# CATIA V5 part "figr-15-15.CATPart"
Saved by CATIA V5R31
Part number: Part1
Bounding box of the stored display mesh (mm): x -75 to 75, y -66.397 to 33.603, z 0 to 1
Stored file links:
  D:\PROJECTS\Project 2021\US EDITION\CATIA V5 6R 2021\Resources\Part Files\c15_catia_v5_6r2021_prt\figr-15-15.CATPart
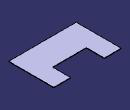
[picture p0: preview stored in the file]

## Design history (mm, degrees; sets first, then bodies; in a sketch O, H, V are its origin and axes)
SheetMetalParameters1: Thickness 1, BendRadius 1, KFactor 0.325257 {= log(min(100,max(20*SheetMetalParameters1.BendRadius,SheetMetalParameters1.Thickness)/SheetMetalParameters1.Thickness))/log(100)/2}, ReliefRadialLength 1, ReliefAxialLength 2, MinimumBendRadius 0
Body1 (main body)
  Sketch1 on xy-plane, origin (0, 0, 0), H (1, 0, 0), V (0, 1, 0)
    line L1 (-37.5, 33.6029) -> (-37.5, -6.3971)
    line L2 (-37.5, -6.3971) -> (37.5, -6.3971)
    line L3 (37.5, -6.3971) -> (37.5, 33.6029)
    line L4 (37.5, 33.6029) -> (75, 33.6029)
    line L5 (75, 33.6029) -> (75, -66.3971)
    line L6 (75, -66.3971) -> (-75, -66.3971)
    line L7 (-75, -66.3971) -> (-75, 33.6029)
    point P8 (-75, 33.6029)
    line L8 (-75, 33.6029) -> (-37.5, 33.6029)
    length L7 = 100
    length L1 = 40
    length L6 = 150
    distance L1 L3 = 75
    vertical: L1 V, L3 V, L5 V, L7 V
    horizontal: L2 H, L4 H, L6 H, L8 H
    coincidence: P8 L4
    symmetry: L7 L5 V, L1 L3 V
  Wall1: Thickness 1, Profile Sketch1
